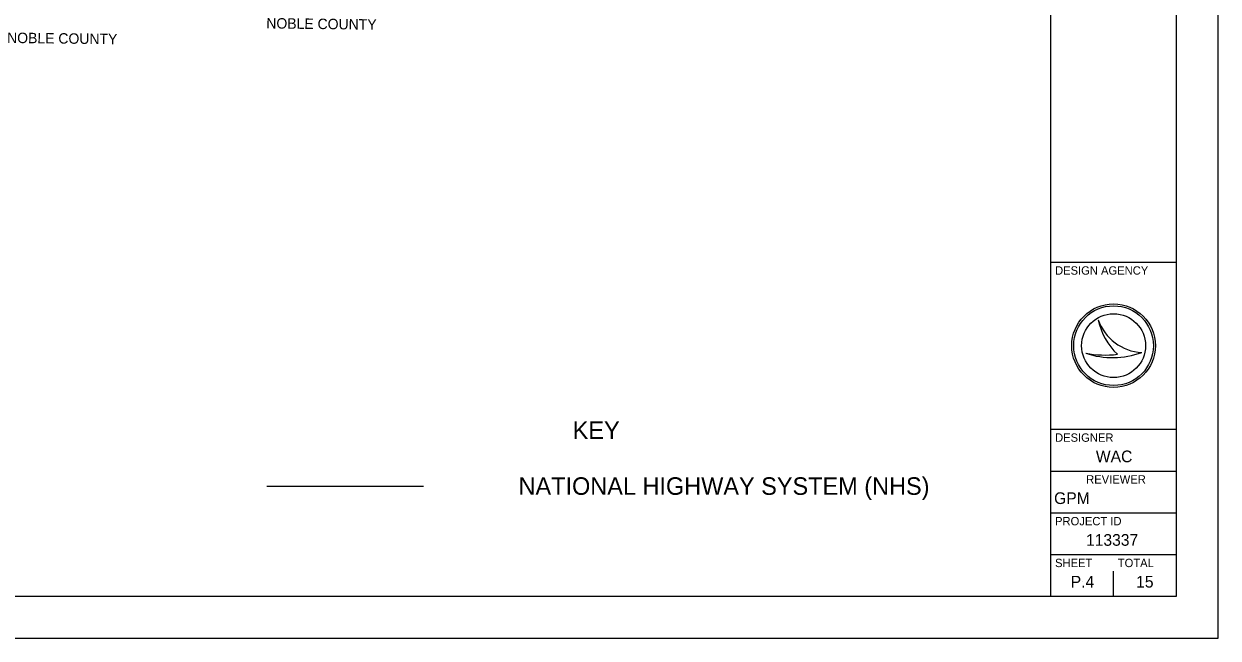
# Model space of a CAD drawing. Extents: x 2125567 to 2397567, y 653347 to 829347.
# Drawn here: x 2283311 to 2397567, y 653347 to 712158 of the extents above; entities that cross this region are included whole.
import ezdxf

# ---------------------------------------------------------------- set-up
doc = ezdxf.new("R2010")
doc.units = 0
for name, color, linetype in [('GM_X_County_Text', 7, 'Continuous'), ('SH_Border', 7, 'Continuous'), ('SH_Cut_Line', 7, 'Continuous'), ('SH_Data', 7, 'Continuous'), ('UT_P_Electric', 7, 'Continuous')]:
    doc.layers.add(name, color=color, linetype=linetype)

msp = doc.modelspace()

# ---------------------------------------------------------------- linework, layer by layer
at = {"layer": 'SH_Border'}
for p, q in [((2381567, 657347), (2381567, 825347)), ((2381567, 689347), (2393567, 689347)), ((2381567, 673347), (2393567, 673347)), ((2381567, 669347), (2393567, 669347)), ((2381567, 665347), (2393567, 665347)), ((2381567, 661347), (2393567, 661347))]:
    msp.add_line(p, q, dxfattribs=at)
msp.add_lwpolyline([(2137567, 825347), (2393567, 825347), (2393567, 657347), (2137567, 657347)], close=True, dxfattribs=at)
at = {"layer": 'SH_Cut_Line'}
msp.add_lwpolyline([(2125567, 653347), (2397567, 653347), (2397567, 829347), (2125567, 829347)], close=True, dxfattribs=at)
at = {"layer": 'SH_Data'}
for p, q in [((2386107, 683823), (2386107, 683823)), ((2387567, 681347), (2387567, 681347)), ((2384905, 680623), (2384904, 680623)), ((2390265, 680695), (2390266, 680695)), ((2387567, 657347), (2387567, 659747)), ((2384567, 658747), (2384567, 658747))]:
    msp.add_line(p, q, dxfattribs=at)
for radius in [4000, 3814, 3814, 3058]:
    msp.add_circle((2387567, 681347), radius, dxfattribs=at)
for centre, radius, start, end in [((2390495, 685328), 4639, 198.92567, 198.93195), ((2392341, 685107), 6365, 191.63793, 191.64215), ((2390495, 685328), 4639, 198.93195, 267.16574), ((2392341, 685107), 6365, 191.64215, 226.09467), ((2387483, 688307), 8105, 251.45274, 251.45764), ((2387483, 688307), 8105, 251.45764, 290.08324), ((2386751, 690581), 10128, 259.49639, 259.49952), ((2386751, 690581), 10128, 259.49952, 276.66723)]:
    msp.add_arc(centre, radius, start, end, dxfattribs=at)
at = {"layer": 'UT_P_Electric'}
msp.add_line((2306556, 667907), (2321556, 667907), dxfattribs=at)

# ---------------------------------------------------------------- texts
at = {"layer": 'GM_X_County_Text'}
for p in [(2306500, 711723), (2281699, 710333)]:
    msp.add_text('NOBLE COUNTY', height=1000, rotation=359.28458, dxfattribs=at).set_placement(p)
at = {"layer": 'SH_Data'}
for s, height, p in [('DESIGN AGENCY', 800, (2381967, 688147)), ('DESIGNER', 800, (2381967, 672147)), ('WAC', 1120, (2385871, 670187)), ('REVIEWER', 800, (2384942, 668147)), ('GPM', 1120, (2381874, 666187)), ('PROJECT ID', 800, (2381967, 664147)), ('113337', 1120, (2384926, 662187)), ('SHEET', 800, (2381967, 660147)), ('TOTAL', 800, (2387967, 660147)), ('P.4', 1120, (2383467, 658187)), ('15', 1120, (2389725, 658187))]:
    msp.add_text(s, height=height, dxfattribs=at).set_placement(p)
at = {"layer": 'UT_P_Electric'}
for s, p in [('KEY', (2335819, 672414)), ('NATIONAL HIGHWAY SYSTEM (NHS)', (2330636, 667067))]:
    msp.add_text(s, height=1680, dxfattribs=at).set_placement(p)

doc.saveas('drawing.dxf')
